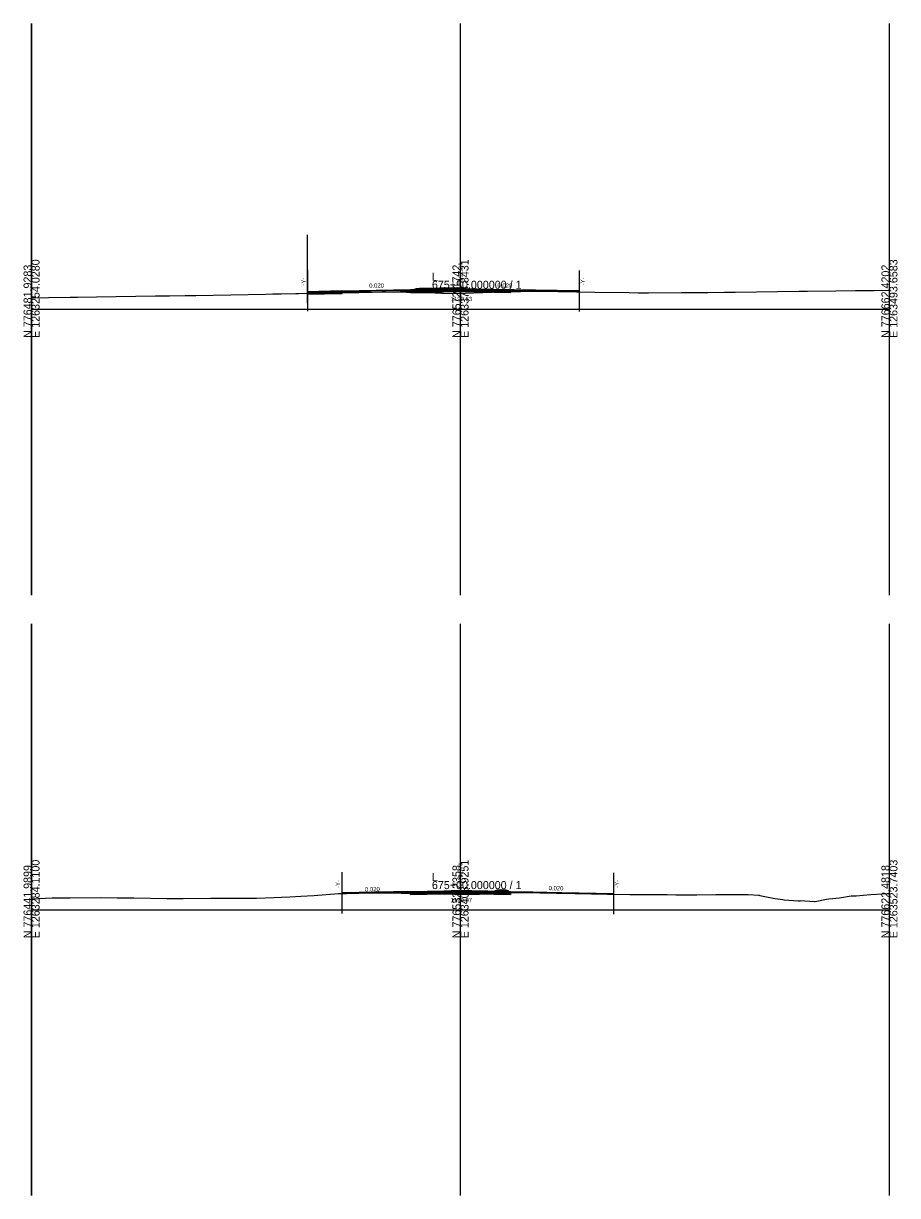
# Model space of a CAD drawing. Extents: x -41 to 1262860, y -100 to 777489.
# Drawn here: x 497.2 to 802.8, y 970 to 1380 of the extents above; entities that cross this region are included whole.
import ezdxf

# ---------------------------------------------------------------- set-up
doc = ezdxf.new("R2010")
doc.units = 0
for name, color, linetype in [('Exist Cross Section Cell', 7, 'Continuous'), ('Exist XS Center Line Elevation Label', 7, 'Continuous'), ('Exist XS Ground Line', 7, 'Continuous'), ('Prop CMT Pvmt Course 1', 7, 'Continuous'), ('Prop CMT Pvmt Course 4', 7, 'Continuous'), ('Prop CMT Pvmt Surface', 7, 'Continuous'), ('Prop CMT Shear Line', 7, 'Continuous'), ('Prop CMT Shld Paved Course 1', 7, 'Continuous'), ('Prop CMT Shld Paved Course 2', 7, 'Continuous'), ('Prop CMT Shld Paved Course 4', 7, 'Continuous'), ('Prop CMT Subgrade Earthwork', 7, 'Continuous'), ('Prop Conc Curb and Gutter', 7, 'Continuous'), ('Prop Conc Island Cover', 7, 'Continuous'), ('Prop XS Earthwork Shape', 7, 'Continuous'), ('Prop XS Exc Vertical Line 1', 7, 'Continuous'), ('Prop XS Exc Vertical Line 2', 7, 'Continuous'), ('Prop XS Exc Vertical Line 3', 7, 'Continuous'), ('Prop XS Hydro Elevations', 7, 'Continuous'), ('Prop XS SE Text', 7, 'Continuous'), ('Scratch_Level_4', 7, 'Continuous'), ('Scratch_Level_5', 7, 'Continuous'), ('Scratch_Level_6', 7, 'Continuous')]:
    doc.layers.add(name, color=color, linetype=linetype)

msp = doc.modelspace()

# ---------------------------------------------------------------- linework, layer by layer
at = {"layer": 'Exist Cross Section Cell'}
for p, q in [((650, 1280), (650, 1290)), ((500, 1280), (650, 1280)), ((650, 1280), (800, 1280)), ((650, 1070), (650, 1080)), ((500, 1070), (650, 1070)), ((650, 1070), (800, 1070))]:
    msp.add_line(p, q, dxfattribs=at)
at = {"layer": 'Exist XS Ground Line'}
for points in [[(500, 1284.05), (505.96, 1284.15), (513.51, 1284.26), (516.06, 1284.31), (522.7, 1284.41), (543.32, 1284.68), (548.27, 1284.74), (553.67, 1284.82), (557.5, 1284.87), (581.88, 1285.36), (584.42, 1285.41), (586.68, 1285.45), (587.23, 1285.44), (592.42, 1285.55), (593.48, 1285.52), (602.25, 1285.73), (606.93, 1285.81), (614.5, 1285.94), (623.81, 1286.15), (631.09, 1285.96), (641.19, 1285.76), (643.35, 1285.7), (648.59, 1285.58), (660.84, 1285.97), (666.5, 1286.23), (669.75, 1286.22), (677.6, 1286.34), (696.97, 1286.05), (708.95, 1285.88), (712.25, 1285.8), (713.61, 1285.79), (715.74, 1285.8), (727.33, 1285.86), (736.06, 1285.92), (736.53, 1285.92), (742.3, 1285.97), (743.15, 1285.97), (743.5, 1285.95), (745.43, 1285.97), (746.11, 1285.98), (768.41, 1286.32), (771.37, 1286.35), (781.27, 1286.5), (788.1, 1286.53), (794.71, 1286.6), (800, 1286.68)], [(500, 1073.77), (507.23, 1074.09), (511.09, 1074.19), (513.46, 1074.2), (523.94, 1074.21), (529.98, 1074.2), (535.77, 1074.09), (547.28, 1073.89), (551.88, 1073.92), (553.02, 1073.96), (562.74, 1073.98), (568.99, 1073.97), (576.63, 1073.99), (577.45, 1073.99), (577.65, 1074), (578.67, 1074.03), (584.88, 1074.25), (587.42, 1074.32), (590.27, 1074.47), (594.17, 1074.72), (598.69, 1075), (607.36, 1075.65), (610.01, 1075.69), (613.14, 1075.8), (617.4, 1075.86), (641.48, 1075.62), (641.57, 1075.62), (641.75, 1075.61), (647.88, 1075.43), (648.24, 1075.31), (648.54, 1075.35), (656.59, 1075.43), (666.19, 1075.93), (672.14, 1076), (677.78, 1076.11), (683.56, 1076), (701.45, 1075.42), (709.26, 1075.27), (722.33, 1075.26), (725.35, 1075.24), (728.05, 1075.19), (731.02, 1075.15), (732.64, 1075.15), (739.28, 1075.33), (741.4, 1075.33), (743.5, 1075.32), (750.55, 1075.26), (754.22, 1075.05), (754.46, 1075.04), (754.72, 1075.01), (759.92, 1073.96), (762.75, 1073.55), (763.14, 1073.49), (768.11, 1073.08), (768.73, 1073.06), (768.82, 1073.2), (773.82, 1072.82), (773.92, 1072.81), (773.98, 1072.81), (774.05, 1072.82), (778.02, 1073.67), (778.84, 1073.77), (782.54, 1074.14), (786.63, 1074.8), (788.34, 1074.9), (790.86, 1075.09), (793.51, 1075.33), (799.38, 1075.67), (800, 1075.7)]]:
    msp.add_lwpolyline(points, dxfattribs=at)
at = {"layer": 'Prop CMT Pvmt Course 1'}
msp.add_line((608.51, 1286.16), (596.5, 1285.92), dxfattribs=at)
for points in [[(608.5, 1286.41), (608.5, 1286.41), (622.55, 1286.69), (622.55, 1286.69), (622.55, 1286.69), (628.86, 1286.82), (632.5, 1286.89), (632.5, 1286.89), (632.5, 1286.89), (632.5, 1286.64), (632.5, 1286.64), (628.86, 1286.57), (622.55, 1286.44), (622.55, 1286.44), (622.55, 1286.44), (608.5, 1286.16), (608.5, 1286.41)], [(632.5, 1286.64), (650, 1286.99), (667.5, 1286.64)], [(691.5, 1286.41), (691.5, 1286.41), (668.55, 1286.87), (668.55, 1286.87), (668.55, 1286.87), (668.44, 1286.87), (667.5, 1286.89), (667.5, 1286.89), (667.5, 1286.64), (668.44, 1286.62), (668.55, 1286.62), (668.55, 1286.62), (668.55, 1286.62), (691.5, 1286.16), (691.5, 1286.41)], [(608.5, 1075.91), (608.5, 1075.66), (632.5, 1076.14), (632.5, 1076.14), (632.5, 1076.39), (632.5, 1076.39), (632.5, 1076.39), (608.5, 1075.91), (608.5, 1075.91)], [(632.5, 1076.14), (650, 1076.49), (667.5, 1076.14)], [(703.5, 1075.67), (703.5, 1075.42), (690.11, 1075.69), (690.11, 1075.69), (690.11, 1075.69), (675.25, 1075.99), (675.14, 1075.99), (675.14, 1075.99), (667.5, 1076.14), (667.5, 1076.14), (667.5, 1076.39), (667.5, 1076.39), (667.5, 1076.39), (675.14, 1076.24), (675.14, 1076.24), (675.25, 1076.24), (690.11, 1075.94), (690.11, 1075.94), (690.11, 1075.94), (703.5, 1075.67), (703.5, 1075.67)]]:
    msp.add_lwpolyline(points, dxfattribs=at)
at = {"layer": 'Prop CMT Pvmt Course 4'}
for p, q in [((608.5, 1285.37), (596.52, 1285.13)), ((608.5, 1285.37), (608.5, 1285.83)), ((632.5, 1286.31), (632.5, 1285.85)), ((667.5, 1285.85), (667.5, 1286.31))]:
    msp.add_line(p, q, dxfattribs=at)
msp.add_lwpolyline([(632.5, 1285.85), (650, 1286.2), (667.5, 1285.85)], dxfattribs=at)
at = {"layer": 'Prop CMT Pvmt Surface'}
msp.add_line((608.5, 1286.41), (596.5, 1286.17), dxfattribs=at)
for points in [[(608.5, 1286.41), (632.5, 1286.89), (650, 1287.24), (667.5, 1286.89), (691.5, 1286.41)], [(608.5, 1075.91), (632.5, 1076.39)], [(632.5, 1076.39), (650, 1076.74), (667.5, 1076.39)], [(667.5, 1076.39), (703.5, 1075.67)]]:
    msp.add_lwpolyline(points, dxfattribs=at)
at = {"layer": 'Prop CMT Shear Line'}
for p, q in [((596.5, 1293.85), (596.5, 1279.41)), ((691.5, 1293.63), (691.5, 1279.19)), ((608.5, 1083.13), (608.5, 1068.69)), ((703.5, 1082.89), (703.5, 1068.45))]:
    msp.add_line(p, q, dxfattribs=at)
at = {"layer": 'Prop CMT Shld Paved Course 1'}
msp.add_lwpolyline([(646.7, 1076.67), (646.7, 1076.67), (650, 1076.74), (650, 1076.74), (653.58, 1076.67), (653.58, 1076.67), (653.88, 1076.66), (654.91, 1076.64), (654.91, 1076.64), (654.91, 1076.64), (654.91, 1076.64), (659.55, 1076.55)], dxfattribs=at)
at = {"layer": 'Prop CMT Shld Paved Course 2'}
for p, q in [((608.5, 1285.83), (596.51, 1285.59)), ((614.5, 1286.28), (608.5, 1286.16)), ((608.5, 1286.16), (608.5, 1286.16)), ((608.5, 1286.16), (608.5, 1286.16)), ((608.5, 1286.16), (608.5, 1285.84)), ((608.5, 1285.84), (611.27, 1285.88)), ((608.5, 1285.83), (608.5, 1285.84)), ((608.5, 1285.84), (608.5, 1285.84)), ((611.27, 1285.88), (614.5, 1285.95)), ((611.27, 1285.88), (611.27, 1285.88)), ((611.27, 1285.88), (611.27, 1285.88)), ((622.55, 1286.44), (614.5, 1286.28)), ((614.5, 1286.28), (614.5, 1286.28)), ((614.5, 1286.28), (614.5, 1286.28)), ((614.5, 1285.95), (618.21, 1286.02)), ((614.5, 1285.95), (614.5, 1285.95)), ((618.21, 1286.02), (622.55, 1286.12)), ((618.21, 1286.02), (618.21, 1286.02)), ((623.81, 1286.47), (622.55, 1286.44)), ((622.55, 1286.44), (622.55, 1286.44)), ((622.55, 1286.44), (622.55, 1286.44)), ((622.55, 1286.12), (623.81, 1286.15)), ((622.55, 1286.12), (622.55, 1286.12)), ((622.55, 1286.12), (622.55, 1286.12)), ((628.86, 1286.57), (623.81, 1286.47)), ((623.81, 1286.47), (623.81, 1286.47)), ((623.81, 1286.15), (624.06, 1286.14)), ((624.06, 1286.14), (628.86, 1286.24)), ((624.06, 1286.14), (624.06, 1286.14)), ((624.06, 1286.14), (624.06, 1286.14)), ((631.09, 1286.61), (628.86, 1286.57)), ((628.86, 1286.57), (628.86, 1286.57)), ((628.86, 1286.24), (631.09, 1286.28)), ((628.86, 1286.24), (628.86, 1286.24)), ((628.86, 1286.24), (628.86, 1286.24)), ((632.5, 1286.64), (631.09, 1286.61)), ((631.09, 1286.61), (631.09, 1286.61)), ((631.09, 1286.28), (632.5, 1286.31)), ((631.09, 1286.28), (631.09, 1286.28)), ((632.5, 1286.31), (632.5, 1286.64)), ((632.5, 1286.64), (632.5, 1286.64)), ((632.5, 1286.64), (632.5, 1286.64)), ((632.5, 1286.31), (632.5, 1286.31)), ((667.5, 1286.31), (667.5, 1286.64)), ((667.5, 1286.64), (667.5, 1286.64)), ((667.5, 1286.64), (668.44, 1286.62)), ((668.44, 1286.29), (667.5, 1286.31)), ((668.44, 1286.62), (668.55, 1286.62)), ((668.55, 1286.29), (668.44, 1286.29)), ((668.55, 1286.62), (668.55, 1286.62)), ((668.55, 1286.62), (669.75, 1286.6)), ((669.75, 1286.26), (668.55, 1286.29)), ((668.55, 1286.29), (668.55, 1286.29)), ((669.75, 1286.6), (669.75, 1286.6)), ((669.75, 1286.6), (669.75, 1286.6)), ((669.75, 1286.6), (677.6, 1286.44)), ((671, 1286.24), (669.75, 1286.26)), ((669.75, 1286.26), (669.75, 1286.26)), ((669.75, 1286.26), (669.75, 1286.26)), ((677.6, 1286.34), (671, 1286.24)), ((671, 1286.24), (671, 1286.24)), ((677.6, 1286.44), (677.6, 1286.44)), ((677.6, 1286.44), (691.5, 1286.16)), ((691.5, 1286.14), (677.6, 1286.34)), ((677.6, 1286.34), (677.6, 1286.34)), ((691.5, 1286.16), (691.5, 1286.16)), ((691.5, 1286.16), (691.5, 1286.16)), ((691.5, 1286.16), (691.5, 1286.14)), ((691.5, 1286.14), (691.5, 1286.14)), ((610.01, 1075.69), (608.5, 1075.66)), ((608.5, 1075.66), (609.25, 1075.68)), ((609.25, 1075.68), (610.01, 1075.69)), ((613.14, 1075.75), (610.01, 1075.69)), ((610.01, 1075.69), (610.21, 1075.69)), ((610.01, 1075.69), (610.01, 1075.69)), ((610.21, 1075.69), (613.14, 1075.75)), ((610.21, 1075.69), (610.21, 1075.69)), ((613.14, 1075.75), (617.4, 1075.84)), ((617.4, 1075.84), (613.14, 1075.75)), ((632.5, 1076.14), (617.4, 1075.84)), ((617.4, 1075.84), (618.01, 1075.85)), ((617.4, 1075.84), (617.4, 1075.84)), ((617.4, 1075.84), (617.4, 1075.84)), ((618.01, 1075.85), (618.01, 1075.85)), ((618.01, 1075.85), (629.24, 1075.74)), ((629.24, 1075.74), (632.5, 1075.81)), ((629.24, 1075.74), (629.24, 1075.74)), ((629.24, 1075.74), (629.24, 1075.74)), ((632.5, 1075.81), (632.5, 1076.14)), ((632.5, 1076.14), (632.5, 1076.14)), ((632.5, 1076.14), (632.5, 1076.14)), ((632.5, 1076.14), (632.5, 1076.14)), ((632.5, 1075.81), (632.5, 1075.81)), ((667.5, 1075.81), (667.5, 1075.94))]:
    msp.add_line(p, q, dxfattribs=at)
for points in [[(632.5, 1286.31), (650, 1286.66), (667.5, 1286.31)], [(632.5, 1075.81), (650, 1076.16), (667.5, 1075.81)], [(690.11, 1075.69), (690.11, 1075.69), (690.11, 1075.69), (701.45, 1075.46), (701.45, 1075.46), (703.5, 1075.42), (703.5, 1075.42), (703.5, 1075.38), (701.45, 1075.42), (701.45, 1075.42), (697.99, 1075.53), (697.99, 1075.53), (690.11, 1075.69), (690.11, 1075.69), (690.11, 1075.69), (683.56, 1075.82), (683.56, 1075.82), (683.56, 1075.82), (677.78, 1075.93), (677.78, 1075.93), (677.78, 1075.93), (677.78, 1075.93), (675.25, 1075.99), (675.25, 1075.99), (675.14, 1075.99), (675.14, 1075.99), (675.14, 1075.99), (673.38, 1076.02), (673.38, 1076.02), (673.38, 1076.02), (672.14, 1076), (672.14, 1076), (667.5, 1075.94), (667.5, 1075.94), (667.5, 1076.14), (667.5, 1076.14), (667.5, 1076.14), (672.14, 1076.05), (672.14, 1076.05), (675.14, 1075.99), (675.14, 1075.99), (675.14, 1075.99), (675.25, 1075.99), (675.25, 1075.99), (677.78, 1075.93), (677.78, 1075.93), (677.78, 1075.93), (677.78, 1075.93), (683.56, 1075.82), (683.56, 1075.82), (683.56, 1075.82), (690.11, 1075.69)]]:
    msp.add_lwpolyline(points, dxfattribs=at)
at = {"layer": 'Prop CMT Shld Paved Course 4'}
for p, q in [((624.06, 1286.14), (631.09, 1285.96)), ((632.5, 1285.93), (631.09, 1285.96)), ((669.75, 1286.22), (667.5, 1286.23)), ((669.75, 1286.22), (671, 1286.24)), ((629.24, 1075.74), (632.5, 1075.71)), ((632.5, 1075.35), (632.5, 1075.81)), ((667.5, 1075.35), (667.5, 1075.81))]:
    msp.add_line(p, q, dxfattribs=at)
msp.add_lwpolyline([(632.5, 1075.35), (650, 1075.7), (667.5, 1075.35)], dxfattribs=at)
at = {"layer": 'Prop CMT Subgrade Earthwork'}
for p, q in [((596.5, 1285.13), (596.5, 1285.59)), ((608.5, 1285.37), (596.5, 1285.13)), ((608.5, 1285.84), (608.5, 1285.37)), ((650, 1286.2), (632.5, 1285.85)), ((632.5, 1285.85), (632.5, 1285.93)), ((667.5, 1285.85), (650, 1286.2)), ((667.5, 1286.23), (667.5, 1285.85)), ((632.5, 1075.35), (632.5, 1075.71)), ((650, 1075.7), (632.5, 1075.35)), ((667.5, 1075.35), (650, 1075.7)), ((667.5, 1075.94), (667.5, 1075.35))]:
    msp.add_line(p, q, dxfattribs=at)
at = {"layer": 'Prop Conc Curb and Gutter'}
for p, q in [((650.67, 1287.63), (649.67, 1287.65)), ((649.67, 1287.65), (649.67, 1287.21)), ((651.42, 1287.38), (650.67, 1287.63)), ((650.67, 1287.63), (650.67, 1287.63)), ((633.87, 1286.92), (633.88, 1287.09)), ((633.87, 1286.92), (633.87, 1286.92)), ((633.87, 1286.92), (633.87, 1286.79)), ((635.63, 1286.92), (633.87, 1286.92)), ((633.87, 1286.92), (633.87, 1286.92)), ((633.87, 1286.79), (633.87, 1286.79)), ((633.87, 1286.79), (635.63, 1286.79)), ((633.88, 1287.09), (634.63, 1287.34)), ((633.88, 1287.09), (633.88, 1287.09)), ((634.63, 1287.34), (635.63, 1287.36)), ((634.63, 1287.34), (634.63, 1287.34)), ((635.63, 1287.36), (635.63, 1286.92)), ((635.63, 1286.79), (635.63, 1286.92)), ((635.63, 1286.92), (635.63, 1286.92)), ((635.63, 1286.79), (635.63, 1286.79)), ((635.63, 1286.79), (635.63, 1286.79)), ((651.43, 1287.21), (649.67, 1287.21)), ((649.67, 1287.21), (649.67, 1287.09)), ((649.67, 1287.21), (649.67, 1287.21)), ((649.67, 1287.09), (649.67, 1287.09)), ((649.67, 1287.09), (651.43, 1287.09)), ((651.43, 1287.21), (651.42, 1287.38)), ((651.42, 1287.38), (651.42, 1287.38)), ((651.43, 1287.09), (651.43, 1287.21)), ((651.43, 1287.21), (651.43, 1287.21)), ((651.43, 1287.21), (651.43, 1287.21)), ((651.43, 1287.09), (651.43, 1287.09)), ((651.43, 1287.09), (651.43, 1287.09)), ((662.17, 1076.5), (662.18, 1076.66)), ((662.17, 1076.5), (662.17, 1076.5)), ((662.17, 1076.5), (662.17, 1076.37)), ((663.93, 1076.5), (662.17, 1076.5)), ((662.17, 1076.5), (662.17, 1076.5)), ((662.17, 1076.37), (662.17, 1076.37)), ((662.17, 1076.37), (663.93, 1076.37)), ((662.18, 1076.66), (662.93, 1076.91)), ((662.18, 1076.66), (662.18, 1076.66)), ((662.93, 1076.91), (663.93, 1076.93)), ((662.93, 1076.91), (662.93, 1076.91)), ((663.93, 1076.93), (663.93, 1076.5)), ((663.93, 1076.37), (663.93, 1076.5)), ((663.93, 1076.5), (663.93, 1076.5)), ((663.93, 1076.37), (663.93, 1076.37)), ((663.93, 1076.37), (663.93, 1076.37)), ((665.99, 1076.82), (664.99, 1076.84)), ((664.99, 1076.84), (664.99, 1076.41)), ((666.75, 1076.41), (664.99, 1076.41)), ((664.99, 1076.41), (664.99, 1076.28)), ((664.99, 1076.41), (664.99, 1076.41)), ((664.99, 1076.28), (664.99, 1076.28)), ((664.99, 1076.28), (666.75, 1076.28)), ((666.74, 1076.57), (665.99, 1076.82)), ((665.99, 1076.82), (665.99, 1076.82)), ((666.75, 1076.41), (666.74, 1076.57)), ((666.74, 1076.57), (666.74, 1076.57)), ((666.75, 1076.28), (666.75, 1076.41)), ((666.75, 1076.41), (666.75, 1076.41)), ((666.75, 1076.41), (666.75, 1076.41)), ((666.75, 1076.28), (666.75, 1076.28)), ((666.75, 1076.28), (666.75, 1076.28))]:
    msp.add_line(p, q, dxfattribs=at)
at = {"layer": 'Prop Conc Island Cover'}
for p, q in [((635.63, 1287.36), (649.67, 1287.65)), ((635.63, 1287.11), (649.67, 1287.4)), ((649.67, 1287.4), (649.67, 1287.65)), ((649.67, 1287.65), (649.67, 1287.65)), ((649.67, 1287.4), (649.67, 1287.4)), ((635.63, 1287.36), (635.63, 1287.11)), ((663.93, 1076.93), (663.93, 1076.68)), ((664.99, 1076.84), (663.93, 1076.93)), ((664.99, 1076.59), (663.93, 1076.68)), ((664.99, 1076.59), (664.99, 1076.84)), ((664.99, 1076.84), (664.99, 1076.84)), ((664.99, 1076.59), (664.99, 1076.59))]:
    msp.add_line(p, q, dxfattribs=at)
at = {"layer": 'Prop XS Earthwork Shape'}
for points in [[(608.5, 1285.84), (608.5, 1285.37), (596.5, 1285.13), (596.5, 1285.59), (602.25, 1285.73), (606.93, 1285.81)], [(634.47, 1285.89), (632.5, 1285.85), (632.5, 1285.93)], [(650, 1286.2), (634.47, 1285.89), (641.19, 1285.76), (643.35, 1285.7), (648.59, 1285.58), (660.84, 1285.97), (661.02, 1285.98)], [(661.02, 1285.98), (666.5, 1286.23), (667.5, 1286.23), (667.5, 1285.85)], [(632.5, 1075.35), (632.5, 1075.71), (641.48, 1075.62), (641.57, 1075.62), (641.75, 1075.61), (643.35, 1075.57)], [(648.24, 1075.31), (648.54, 1075.35), (656.59, 1075.43), (658.51, 1075.53), (650, 1075.7), (643.35, 1075.57), (647.88, 1075.43)], [(667.5, 1075.35), (658.51, 1075.53), (666.19, 1075.93), (667.5, 1075.94)]]:
    msp.add_lwpolyline(points, close=True, dxfattribs=at)
at = {"layer": 'Prop XS Exc Vertical Line 1'}
for p, q in [((500, 1180), (500, 1380)), ((500, 970), (500, 1170))]:
    msp.add_line(p, q, dxfattribs=at)
at = {"layer": 'Prop XS Exc Vertical Line 2'}
for p, q in [((650, 1180), (650, 1380)), ((650, 970), (650, 1170))]:
    msp.add_line(p, q, dxfattribs=at)
at = {"layer": 'Prop XS Exc Vertical Line 3'}
for p, q in [((800, 1180), (800, 1380)), ((800, 970), (800, 1170))]:
    msp.add_line(p, q, dxfattribs=at)
at = {"layer": 'Scratch_Level_4'}
for p, q in [((800, 1180), (800, 1380)), ((800, 970), (800, 1170))]:
    msp.add_line(p, q, dxfattribs=at)
at = {"layer": 'Scratch_Level_5'}
msp.add_line((596.5, 1282.15), (596.5, 1306.01), dxfattribs=at)
at = {"layer": 'Scratch_Level_6'}
for p, q in [((500, 1380), (500, 1180)), ((500, 1170), (500, 970))]:
    msp.add_line(p, q, dxfattribs=at)

# ---------------------------------------------------------------- texts
at = {"layer": 'Exist Cross Section Cell'}
for s, p in [('E 1263254.0280', (502.8, 1270)), ('E 1263373.8431', (652.8, 1270)), ('E 1263493.6583', (802.8, 1270)), ('N 776481.9283', (500, 1270)), ('N 776572.1742', (650, 1270)), ('N 776662.4202', (800, 1270)), ('E 1263284.1100', (502.8, 1060)), ('E 1263403.9251', (652.8, 1060)), ('E 1263523.7403', (802.8, 1060)), ('N 776441.9899', (500, 1060)), ('N 776532.2358', (650, 1060)), ('N 776622.4818', (800, 1060))]:
    msp.add_text(s, height=2.8, rotation=90, dxfattribs=at).set_placement(p)
for s, p in [('L', (640, 1290)), ('675+50.000000 / 1', (640, 1287.2)), ('L', (640, 1080)), ('675+00.000000 / 1', (640, 1077.2))]:
    msp.add_text(s, height=2.8, dxfattribs=at).set_placement(p)
at = {"layer": 'Exist XS Center Line Elevation Label'}
for s, p in [('1190.63', (646.58, 1282.88)), ('1190.37', (646.54, 1072.62))]:
    msp.add_text(s, height=1.5, dxfattribs=at).set_placement(p)
at = {"layer": 'Prop XS Hydro Elevations'}
for s, p in [('1192.24', (650.75, 1288.75)), ('-Y-', (595.81, 1288.31)), ('-Y-', (693.46, 1288.4)), ('1191.74', (650.75, 1078.91)), ('-Y-', (607.81, 1077.59)), ('-Y-', (705.46, 1077.66))]:
    msp.add_text(s, height=1.5, rotation=90, dxfattribs=at).set_placement(p)
at = {"layer": 'Prop XS SE Text'}
for rotation, p in [(1.1458, (618.08, 1287.52)), (358.8542, (662.91, 1287.63)), (358.8542, (680.8, 1076.82)), (1.221, (616.62, 1076.36))]:
    msp.add_text('0.020', height=1.5, rotation=rotation, dxfattribs=at).set_placement(p)

doc.saveas('drawing.dxf')
